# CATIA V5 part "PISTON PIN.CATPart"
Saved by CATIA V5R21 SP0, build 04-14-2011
Part number: Part1.3
Bounding box of the stored display mesh (mm): x -42 to 42, y -10 to 10, z -10 to 10
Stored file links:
  G:\CATIA\PROJECT__01\PISTON PIN.CATPart
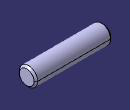
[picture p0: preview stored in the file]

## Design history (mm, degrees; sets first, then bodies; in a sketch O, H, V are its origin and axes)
Body1 (main body)
  Sketch1 on yz-plane, origin (0, 0, 0), H (0, 1, 0), V (0, 0, 1)
    circle A1 centre (0, 0) radius 10
    radius A1 = 10
  Pad1: profile Sketch1, direction (1, 0, 0), length 42, mirrored extent
  Chamfer1: length 2, angle 45, on edge [face of Pad1 from Sketch1.A1 | end face of Pad1]; face of Pad1 from Sketch1.A1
